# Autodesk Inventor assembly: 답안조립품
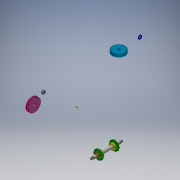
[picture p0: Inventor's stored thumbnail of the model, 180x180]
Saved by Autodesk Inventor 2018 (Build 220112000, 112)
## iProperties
Created: 2019-11
Part Number: 답안조립품
Material: 일반
Document SubType Name: Assembly
Designer: USER
Author: USER
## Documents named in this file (14)
- C:\Users\USER\Desktop\491104V1046\답안조립품.iam
- C:\Users\USER\Desktop\491104V1046\V-벨트풀리.ipt
- V-벨트풀리.ipt
- C:\Users\USER\Desktop\491104V1046\너트 M12x1.25.ipt
- C:\Users\USER\Desktop\491104V1046\베어링 6203.ipt
- C:\Users\USER\Desktop\491104V1046\본체.ipt
- C:\Users\USER\Desktop\491104V1046\볼트 M4.ipt
- C:\Users\USER\Desktop\491104V1046\부시.ipt
- C:\Users\USER\Desktop\491104V1046\스퍼기어.ipt
- C:\Users\USER\Desktop\491104V1046\오일 실 26 38 8.ipt
- C:\Users\USER\Desktop\491104V1046\와셔 12x24.ipt
- C:\Users\USER\Desktop\491104V1046\축.ipt
- C:\Users\USER\Desktop\491104V1046\커버.ipt
- C:\Users\USER\Desktop\491104V1046\키 5x5x12.ipt
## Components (1 placed, 1 different names)
1. V-벨트풀리:1
